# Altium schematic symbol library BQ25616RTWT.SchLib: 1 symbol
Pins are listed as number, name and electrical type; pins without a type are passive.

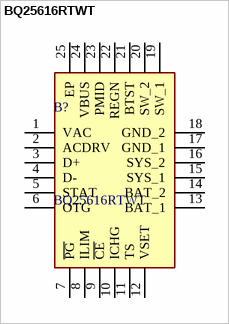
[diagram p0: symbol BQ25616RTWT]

## BQ25616RTWT
designator B?
Battery Management Standalone 1-cell 3.0-A buck battery charger with power path and 1.2-A boost operation 24-WQFN -40 to 85; Manufacturer_Name: Texas Instruments; Geometry.Height: 0.8mm
footprint QFN50P400X400X80-25N-D
pins: 1 VAC, 2 ACDRV, 3 D+, 4 D-, 5 STAT, 6 OTG, 7 ~{PG}, 8 ILIM, 9 ~{CE}, 10 ICHG, 11 TS, 12 VSET, 13 BAT_1, 14 BAT_2, 15 SYS_1, 16 SYS_2, 17 GND_1, 18 GND_2, 19 SW_1, 20 SW_2, 21 BTST, 22 REGN, 23 PMID, 24 VBUS, 25 EP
